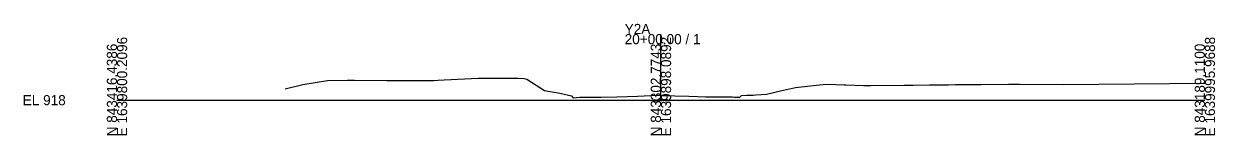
# Model space of a CAD drawing. Extents: x -26 to 303, y -10 to 10517.
# Drawn here: x -25.7 to 302.8, y 9490.3 to 9521.1 of the extents above; entities that cross this region are included whole.
import ezdxf

# ---------------------------------------------------------------- set-up
doc = ezdxf.new("R2010")
doc.units = 0
for name, color, linetype in [('Exist Cross Section Cell', 7, 'Continuous'), ('Exist XS Center Line Elevation Label', 7, 'Continuous'), ('Exist XS Ground Line', 7, 'Continuous')]:
    doc.layers.add(name, color=color, linetype=linetype)

msp = doc.modelspace()

# ---------------------------------------------------------------- linework, layer by layer
at = {"layer": 'Exist Cross Section Cell'}
for p, q in [((150, 9500), (150, 9518.26)), ((0, 9500), (150, 9500)), ((150, 9500), (300, 9500))]:
    msp.add_line(p, q, dxfattribs=at)
at = {"layer": 'Exist XS Ground Line'}
msp.add_lwpolyline([(46.39, 9503.12), (51.21, 9504.3), (58.07, 9505.47), (63.43, 9505.48), (65.49, 9505.5), (74.37, 9505.42), (75.62, 9505.4), (76.64, 9505.39), (81.9, 9505.44), (84.18, 9505.43), (87.36, 9505.47), (88.55, 9505.54), (90.18, 9505.63), (99.71, 9506.03), (103.55, 9506.09), (110.59, 9506.03), (112.27, 9506), (113.02, 9505.8), (117.87, 9502.7), (122.09, 9501.9), (125.3, 9501.17), (125.8, 9500.67), (126.75, 9500.73), (127.68, 9500.79), (133.48, 9500.86), (137.81, 9500.92), (143.54, 9501.12), (149.07, 9501.33), (150, 9501.3), (157.71, 9501.07), (160.14, 9501), (162.25, 9500.96), (169.76, 9500.88), (170.22, 9500.86), (171.72, 9500.8), (172.21, 9501.3), (173.72, 9501.36), (175.43, 9501.41), (176.18, 9501.45), (179.09, 9501.61), (182.98, 9502.61), (187.1, 9503.46), (193.74, 9504.2), (195.74, 9504.38), (200.52, 9504.25), (201.03, 9504.23), (205.83, 9504.04), (207.92, 9504.08), (217.01, 9504.16), (219.55, 9504.18), (224.1, 9504.24), (229.4, 9504.26), (231.2, 9504.28), (232.75, 9504.29), (238.29, 9504.31), (245.84, 9504.38), (248.86, 9504.38), (260.97, 9504.35), (300, 9504.68)], dxfattribs=at)

# ---------------------------------------------------------------- texts
at = {"layer": 'Exist Cross Section Cell'}
for s, p in [('Y2A', (140, 9518.26)), ('20+00.00 / 1', (140, 9515.46)), ('EL 918', (-26, 9498.6))]:
    msp.add_text(s, height=2.8, dxfattribs=at).set_placement(p)
for s, p in [('N 843416.4386', (0, 9490)), ('E 1639800.2096', (2.8, 9490)), ('N 843302.7743', (150, 9490)), ('E 1639898.0892', (152.8, 9490)), ('N 843189.1100', (300, 9490)), ('E 1639995.9688', (302.8, 9490))]:
    msp.add_text(s, height=2.8, rotation=90, dxfattribs=at).set_placement(p)
at = {"layer": 'Exist XS Center Line Elevation Label'}
msp.add_text('919.30', height=1, dxfattribs=at).set_placement((147.92, 9499.32))

doc.saveas('drawing.dxf')
